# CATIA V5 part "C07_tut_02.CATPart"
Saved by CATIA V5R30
Part number: Part1
Bounding box of the stored display mesh (mm): x 0 to 32, y -32 to 32, z -15 to 36
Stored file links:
  D:\PROJECTS\CATIA V56R 2020\Resources\c07\C07_tut_02.CATPart
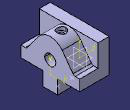
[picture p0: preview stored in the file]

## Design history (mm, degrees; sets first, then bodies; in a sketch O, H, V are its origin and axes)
Body1 (main body)
  Sketch1 on zx-plane, origin (0, 0, 0), H (-1, 0, 0), V (0, 0, 1)
    point P1 (0, 36)
    line L1 (0, 36) -> (0, 0)
    line L2 (0, 0) -> (-32, 0)
    line L3 (0, 36) -> (-12, 36)
    line L4 (-12, 36) -> (-12, 12)
    line L5 (-12, 12) -> (-32, 12)
    line L6 (-32, 12) -> (-32, 0)
    length L2 = 32
    length L3 = 12
    length L6 = 12
    distance L3 L2 = 36
    coincidence: P1 V
    vertical: L1 V, L4 V, L6 V
    horizontal: L2 H, L3 H, L5 H
  Pad1: profile Sketch1, direction (0, 1, 0), length 32, mirrored extent
  Sketch2 on face of Pad1 from Sketch1.L6, origin (32, 0, 0), H (0, 1, 0), V (0, 0, 1)
    arc A1 centre (0, 20) radius 16 from (12.9443, 29.4046) to (-12.9443, 29.4046) ccw
    point P1 (0, 20)
    reference projected line E1 (-32, 36) -> (32, 36) from edge [face of Pad1 from Sketch1.L4 | face of Pad1 from Sketch1.L3]
    line L1 (-25.5894, 12) -> (25.5894, 12)
    point P2 (-25.5894, 12)
    point P3 (25.5894, 12)
    reference projected line E2 (-32, 12) -> (32, 12) from edge [face of Pad1 from Sketch1.L6 | face of Pad1 from Sketch1.L5]
    line L2 (-25.5894, 12) -> (-12.9443, 29.4046)
    line L3 (25.5894, 12) -> (12.9443, 29.4046)
    radius A1 = 16
    angle L3 L2 = 72
    coincidence: P1 V, L1 E2
    tangency: A1 E1, L2 A1, L3 A1
    horizontal: L1 H
    symmetry: P3 P2 V
  Pad2: profile Sketch2, direction (1, 0, 0), up to the existing solid (limit type 2)
  Sketch3 on face of Pad2, origin (32, 0, 0), H (0, 1, 0), V (0, 0, 1)
    line L1 (-8, 0) -> (8, 0)
    line L2 (8, 0) -> (8, -15)
    line L3 (8, -15) -> (-8, -15)
    line L4 (-8, -15) -> (-8, 0)
    reference projected line E1 (-32, 0) -> (32, 0) from edge [face of Pad1 from Sketch1.L2 | face of Pad1 from Sketch1.L6]
    length L2 = 15
    length L3 = 16
    horizontal: L1 H, L3 H
    vertical: L2 V, L4 V
    symmetry: L2 L4 V
    coincidence: L1 E1
  Pad3: profile Sketch3, direction (1, 0, 0), up to face of Pad1 from Sketch1.L1
  Sketch4 on zx-plane, origin (0, 0, 0), H (-1, 0, 0), V (0, 0, 1)
    point P1 (-20, 36)
    reference projected line E1 (0, 36) -> (-12, 36) from edge [face of Pad1 from Sketch1.L3 | end face of Pad1]
    reference projected line E2 (0, 0) -> (0, 36) from edge [face of Pad1 from Sketch1.L1 | end face of Pad1]
    distance P1 E2 = 20
    coincidence: P1 E1
  Sketch5 on {plane type Tangent, Support face of Pad2 from Sketch2.A1, RefPoint Sketch4.P1}, origin (20, 0, 36), H (1, 0, 0), V (0, -1, 0)
    point P1 (0, 0)
    reference projected point E1 (0, 0) from Sketch4.P1
    coincidence: E1 P1
  Hole1: placed by Sketch5, at (20, 0, 36) direction (0, 0, -1), diameter 6, depth 16, V-bottom angle 120, counterbore diameter 10, counterbore depth 4
  Sketch6 on face of Pad2, origin (32, 0, 0), H (0, 1, 0), V (0, 0, 1)
    point P1 (0, 14)
    reference projected line E1 (-8, -15) -> (8, -15) from edge [face of Pad3 from Sketch3.L3 | start face of Pad3]
    distance P1 E1 = 29
    coincidence: P1 V
  Sketch7 on face of Pad2, origin (32, 0, 10), H (0, 1, 0), V (0, 0, 1)
    point P1 (0, 4)
    reference projected point E1 (0, 4) from Sketch6.P1
    coincidence: E1 P1
  Hole2: placed by Sketch7, at (32, 0, 14) direction (-1, 0, 0), diameter 12, depth 24
  Fillet1: radius 3, on edge [face of Pad1 from Sketch1.L5 | face of Pad2 from Sketch2.L3]; edge [face of Pad2 from Sketch2.L2 | face of Pad1 from Sketch1.L5]
  Sketch8 on zx-plane, origin (0, 0, 0), H (-1, 0, 0), V (0, 0, 1)
    point P1 (-24, -15)
    point P2 (-8, -15)
    reference projected line E1 (-32, -15) -> (0, -15) from edge [face of Pad3 from Sketch3.L3 | face of Pad3 from Sketch3.L2]
    reference projected line E2 (-32, -15) -> (0, -15) from edge [face of Pad3 from Sketch3.L3 | face of Pad3 from Sketch3.L2]
    reference projected line E3 (-32, -15) -> (-32, 0) from edge [face of Pad3 from Sketch3.L2 | face of Pad2]
    distance E3 P1 = 8
    distance P2 P1 = 16
    coincidence: P1 E1, P2 E2
  Sketch9 on face of Pad3 from Sketch3.L3, origin (8, 0, -15), H (1, 0, 0), V (0, -1, 0)
    point P1 (0, 0)
    reference projected point E1 (0, 0) from Sketch8.P2
    coincidence: E1 P1
  Hole3: placed by Sketch9, at (8, 0, -15) direction (0, 0, 1), diameter 6, depth 16, V-bottom angle 120, threaded, thread diameter 6.6, thread depth 10, pitch 1
  Sketch10 on face of Pad3 from Sketch3.L3, origin (24, 0, -15), H (1, 0, 0), V (0, -1, 0)
    point P1 (0, 0)
    reference projected point E1 (0, 0) from Sketch8.P1
    coincidence: E1 P1
  Hole4: placed by Sketch10, at (24, 0, -15) direction (0, 0, 1), diameter 6, depth 16, V-bottom angle 120, threaded, thread diameter 6.6, thread depth 10, pitch 1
